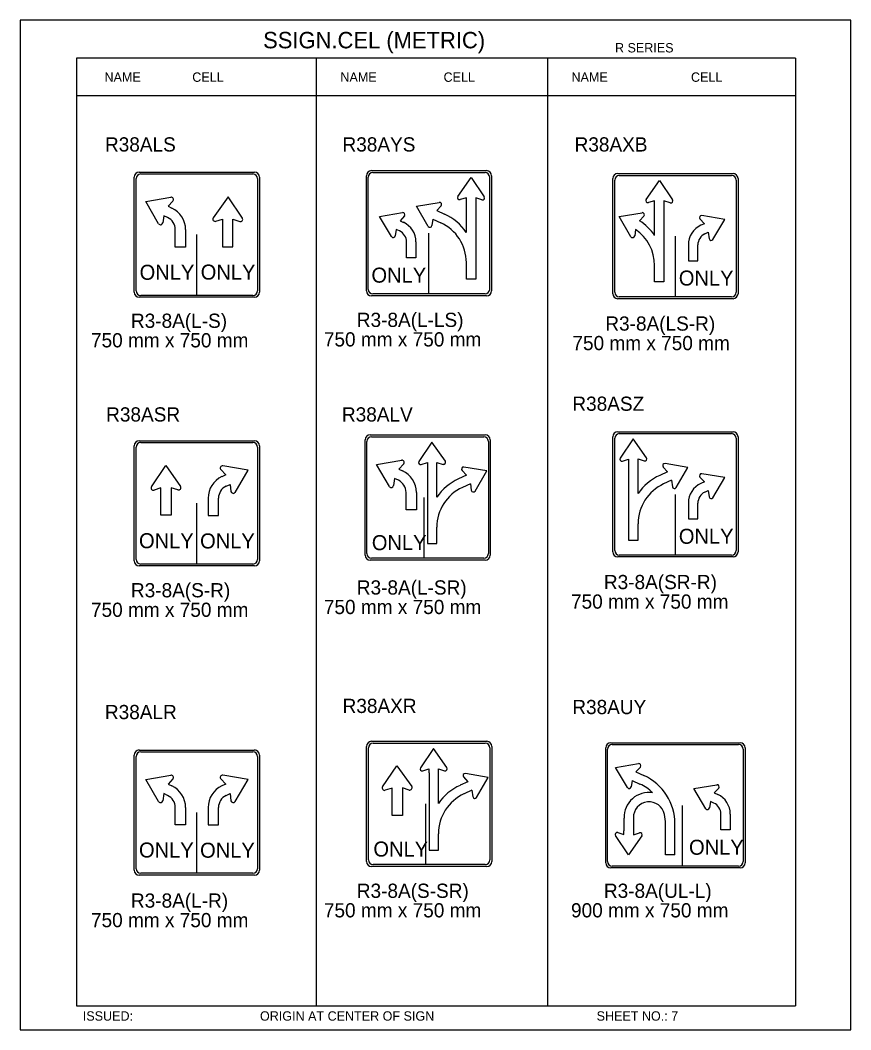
# Model space of a CAD drawing. Extents: x -12 to 6962, y -3756 to 679.
# Drawn here: x -11.9 to 163.4, y -5 to 208 of the extents above; entities that cross this region are included whole.
import ezdxf

# ---------------------------------------------------------------- set-up
doc = ezdxf.new("R2010")
doc.units = 0
for name, color, linetype in [('Level 1', 7, 'Continuous'), ('Level 2', 7, 'Continuous'), ('Level 3', 7, 'Continuous'), ('Level 63', 7, 'Continuous')]:
    doc.layers.add(name, color=color, linetype=linetype)

msp = doc.modelspace()

# ---------------------------------------------------------------- linework, layer by layer
at = {"layer": 'Level 1'}
for p, q in [((151.75, 200), (0, 200)), ((0, 200), (0, 0)), ((50.58, 200), (50.58, 0)), ((99.37, 200), (99.37, 0)), ((151.75, 200), (151.75, 0)), ((151.75, 192.08), (0, 192.08)), ((13.57, 175.59), (37.24, 175.59)), ((61.55, 151.24), (61.55, 174.92)), ((62.53, 175.9), (86.21, 175.9)), ((80.46, 170.82), (83.31, 174.84)), ((83.31, 174.84), (86.05, 170.76)), ((87.18, 174.92), (87.18, 151.24)), ((114.23, 175.68), (138.53, 175.68)), ((114.54, 175.28), (138.22, 175.28)), ((12.59, 150.94), (12.59, 174.61)), ((38.22, 174.61), (38.22, 150.94)), ((113.17, 150.32), (113.17, 174.62)), ((113.56, 150.63), (113.56, 174.31)), ((120.18, 170.21), (123.03, 174.22)), ((123.03, 174.22), (125.77, 170.15)), ((139.19, 174.31), (139.19, 150.63)), ((139.59, 174.62), (139.59, 150.32)), ((14.6, 169.76), (19.93, 170.67)), ((31.98, 170.74), (28.85, 166.32)), ((35, 166.26), (31.98, 170.74)), ((82.26, 170.56), (80.95, 170.17)), ((82.26, 169.74), (82.26, 170.56)), ((85.55, 170.12), (84.24, 170.54)), ((84.24, 170.54), (84.24, 169.75)), ((17.34, 165.09), (14.6, 169.76)), ((20.35, 169.87), (19.33, 168.76)), ((19.33, 168.76), (20.13, 168.4)), ((71.72, 168.76), (76.56, 169.59)), ((74.2, 164.52), (71.72, 168.76)), ((76.94, 168.86), (76.02, 167.85)), ((82.26, 163.24), (82.26, 169.74)), ((84.23, 169.75), (84.23, 153.42)), ((121.98, 169.95), (120.67, 169.55)), ((121.98, 169.13), (121.98, 169.95)), ((121.98, 162.63), (121.98, 169.13)), ((123.95, 169.14), (123.95, 152.81)), ((125.27, 169.5), (123.96, 169.93)), ((123.96, 169.93), (123.96, 169.14)), ((18.41, 166.78), (18.21, 165.29)), ((19.23, 166.4), (18.41, 166.78)), ((63.97, 166.62), (68.81, 167.44)), ((66.45, 162.37), (63.97, 166.62)), ((69.19, 166.72), (68.27, 165.7)), ((76.02, 167.85), (77.68, 167.09)), ((114.51, 166.59), (119.35, 167.42)), ((116.99, 162.35), (114.51, 166.59)), ((119.73, 166.69), (118.82, 165.69)), ((136.78, 166), (131.94, 166.83)), ((29.39, 165.6), (30.83, 166.04)), ((30.83, 166.04), (30.82, 165.13)), ((30.82, 165.13), (30.82, 160.24)), ((33, 160.24), (33, 165.14)), ((33.01, 165.14), (33.01, 166.02)), ((33.01, 166.02), (34.45, 165.55)), ((68.27, 165.7), (68.99, 165.37)), ((75.18, 166.05), (75, 164.69)), ((75.18, 166.05), (76.86, 165.28)), ((131.56, 166.1), (132.48, 165.09)), ((132.48, 165.09), (131.76, 164.76)), ((134.29, 161.76), (136.78, 166)), ((20.85, 160.17), (20.85, 163.86)), ((23.03, 163.85), (23.03, 160.17)), ((25.4, 162.78), (25.4, 162.78)), ((25.4, 162.78), (25.4, 162.78)), ((25.4, 149.96), (25.4, 162.78)), ((67.43, 163.9), (67.25, 162.55)), ((68.18, 163.56), (67.43, 163.9)), ((74.37, 163.08), (74.37, 163.08)), ((74.37, 150.27), (74.37, 163.08)), ((117.97, 163.88), (117.79, 162.52)), ((126.38, 162.47), (126.38, 162.47)), ((126.38, 162.47), (126.38, 162.47)), ((126.38, 149.65), (126.38, 162.47)), ((132.57, 162.95), (133.32, 163.29)), ((133.32, 163.29), (133.5, 161.93)), ((23.03, 160.17), (20.85, 160.17)), ((30.82, 160.24), (33, 160.24)), ((69.65, 157.89), (69.65, 161.25)), ((71.63, 161.24), (71.63, 157.89)), ((129.12, 160.63), (129.12, 157.28)), ((131.1, 157.28), (131.1, 160.64)), ((71.63, 157.89), (69.65, 157.89)), ((82.26, 153.42), (82.26, 156.88)), ((121.98, 152.81), (121.98, 156.26)), ((129.12, 157.28), (131.1, 157.28)), ((84.23, 153.42), (82.26, 153.42)), ((123.95, 152.81), (121.98, 152.81)), ((37.24, 149.96), (13.57, 149.96)), ((86.21, 150.27), (62.53, 150.27)), ((138.53, 149.26), (114.23, 149.26)), ((138.22, 149.65), (114.54, 149.65)), ((62.26, 120.12), (85.93, 120.12)), ((113.56, 96.12), (113.56, 119.8)), ((114.54, 120.78), (138.22, 120.78)), ((117.44, 119.72), (114.69, 115.64)), ((120.29, 115.7), (117.44, 119.72)), ((139.19, 119.8), (139.19, 96.12)), ((12.59, 94.24), (12.59, 117.91)), ((13.57, 118.89), (37.24, 118.89)), ((38.22, 117.91), (38.22, 94.24)), ((61.28, 95.46), (61.28, 119.14)), ((74.99, 118.97), (72.24, 114.9)), ((77.84, 114.96), (74.99, 118.97)), ((86.91, 119.14), (86.91, 95.46)), ((63.29, 114.29), (68.62, 115.2)), ((115.2, 115), (116.5, 115.42)), ((116.5, 115.42), (116.5, 114.63)), ((118.49, 114.62), (118.49, 115.44)), ((118.49, 115.44), (119.8, 115.05)), ((15.81, 109.56), (18.83, 114.04)), ((18.83, 114.04), (21.96, 109.62)), ((30.46, 113.18), (31.48, 112.06)), ((36.2, 113.06), (30.88, 113.97)), ((33.47, 108.39), (36.2, 113.06)), ((66.03, 109.62), (63.29, 114.29)), ((69.04, 114.4), (68.02, 113.29)), ((68.02, 113.29), (68.82, 112.92)), ((72.75, 114.25), (74.05, 114.68)), ((74.05, 114.68), (74.05, 113.88)), ((74.06, 113.88), (74.06, 97.56)), ((76.04, 113.88), (76.04, 114.7)), ((76.04, 114.7), (77.35, 114.3)), ((76.04, 107.38), (76.04, 113.88)), ((81.35, 113), (82.28, 111.99)), ((86.58, 112.9), (81.73, 113.72)), ((116.51, 114.63), (116.51, 98.3)), ((118.49, 108.12), (118.49, 114.62)), ((123.8, 113.74), (124.73, 112.73)), ((129.03, 113.64), (124.18, 114.47)), ((126.54, 109.39), (129.03, 113.64)), ((31.48, 112.06), (30.68, 111.7)), ((67.1, 111.31), (66.9, 109.81)), ((67.92, 110.93), (67.1, 111.31)), ((82.28, 111.99), (80.61, 111.22)), ((84.09, 108.65), (86.58, 112.9)), ((124.73, 112.73), (123.06, 111.97)), ((125.57, 110.93), (123.89, 110.16)), ((125.57, 110.93), (125.74, 109.57)), ((131.56, 111.6), (132.48, 110.58)), ((136.78, 111.5), (131.94, 112.32)), ((134.29, 107.25), (136.78, 111.5)), ((17.79, 109.32), (16.36, 108.85)), ((17.8, 108.44), (17.79, 109.32)), ((21.42, 108.9), (19.98, 109.34)), ((19.98, 109.34), (19.98, 108.43)), ((31.57, 109.7), (32.4, 110.08)), ((32.4, 110.08), (32.59, 108.59)), ((83.12, 110.18), (81.44, 109.42)), ((83.12, 110.18), (83.29, 108.83)), ((132.48, 110.58), (131.76, 110.25)), ((132.57, 108.44), (133.32, 108.78)), ((133.32, 108.78), (133.5, 107.43)), ((17.81, 103.54), (17.81, 108.44)), ((19.98, 108.43), (19.98, 103.54)), ((27.78, 107.15), (27.78, 103.47)), ((29.96, 103.47), (29.96, 107.16)), ((69.54, 104.69), (69.54, 108.39)), ((71.72, 108.38), (71.72, 104.69)), ((73.35, 94.49), (73.35, 107.3)), ((74.09, 107.3), (74.09, 107.3)), ((126.38, 107.96), (126.38, 107.96)), ((126.38, 107.96), (126.38, 107.96)), ((126.38, 95.15), (126.38, 107.96)), ((25.4, 106.08), (25.4, 106.08)), ((25.4, 93.26), (25.4, 106.08)), ((71.72, 104.69), (69.54, 104.69)), ((129.12, 106.12), (129.12, 102.77)), ((131.1, 102.77), (131.1, 106.13)), ((19.98, 103.54), (17.81, 103.54)), ((27.78, 103.47), (29.96, 103.47)), ((129.12, 102.77), (131.1, 102.77)), ((76.04, 97.56), (76.04, 101.01)), ((118.49, 98.3), (118.49, 101.76)), ((116.51, 98.3), (118.49, 98.3)), ((74.06, 97.56), (76.04, 97.56)), ((85.93, 94.49), (62.26, 94.49)), ((138.22, 95.15), (114.54, 95.15)), ((37.24, 93.26), (13.57, 93.26)), ((62.58, 55.45), (86.26, 55.45)), ((13.57, 53.61), (37.24, 53.61)), ((61.61, 30.8), (61.61, 54.47)), ((75.32, 54.3), (72.57, 50.23)), ((78.16, 50.29), (75.32, 54.3)), ((87.24, 54.47), (87.24, 30.8)), ((112.07, 30.49), (112.07, 54.17)), ((113.05, 55.14), (139.71, 55.14)), ((140.69, 54.17), (140.69, 30.49)), ((12.59, 28.96), (12.59, 52.63)), ((38.22, 52.63), (38.22, 28.96)), ((64.59, 46.22), (67.61, 50.7)), ((67.61, 50.7), (70.75, 46.28)), ((73.07, 49.58), (74.38, 50.01)), ((74.38, 50.01), (74.38, 49.22)), ((74.39, 49.22), (74.39, 32.89)), ((76.37, 49.21), (76.36, 50.03)), ((76.36, 50.03), (77.67, 49.63)), ((76.37, 42.71), (76.37, 49.21)), ((86.9, 48.23), (82.06, 49.05)), ((113.76, 50.31), (118.61, 51.14)), ((116.25, 46.06), (113.76, 50.31)), ((118.99, 50.41), (118.06, 49.4)), ((118.06, 49.4), (119.73, 48.64)), ((14.6, 47.78), (19.93, 48.69)), ((17.34, 43.11), (14.6, 47.78)), ((20.35, 47.89), (19.33, 46.78)), ((30.46, 47.89), (31.48, 46.78)), ((36.2, 47.78), (30.88, 48.69)), ((33.47, 43.11), (36.2, 47.78)), ((82.61, 47.32), (80.94, 46.56)), ((81.68, 48.33), (82.61, 47.32)), ((84.42, 43.98), (86.9, 48.23)), ((117.22, 47.6), (117.05, 46.24)), ((117.22, 47.6), (118.9, 46.83)), ((18.41, 44.8), (18.21, 43.31)), ((19.23, 44.42), (18.41, 44.8)), ((19.33, 46.78), (20.13, 46.42)), ((31.48, 46.78), (30.68, 46.42)), ((31.57, 44.42), (32.4, 44.8)), ((32.4, 44.8), (32.59, 43.31)), ((66.58, 45.98), (65.15, 45.51)), ((66.59, 45.1), (66.58, 45.98)), ((66.59, 40.2), (66.59, 45.1)), ((70.21, 45.56), (68.77, 46)), ((68.77, 46), (68.77, 45.09)), ((68.77, 45.09), (68.77, 40.2)), ((83.44, 45.52), (81.77, 44.75)), ((83.44, 45.52), (83.62, 44.16)), ((130.28, 45.86), (135.13, 46.69)), ((132.77, 41.61), (130.28, 45.86)), ((135.51, 45.96), (134.58, 44.95)), ((134.58, 44.95), (135.31, 44.62)), ((73.68, 29.82), (73.68, 42.63)), ((74.42, 42.63), (74.42, 42.63)), ((133.75, 43.15), (133.57, 41.79)), ((134.49, 42.81), (133.75, 43.15)), ((20.85, 38.19), (20.85, 41.88)), ((23.03, 41.87), (23.03, 38.19)), ((25.4, 40.8), (25.4, 40.8)), ((25.4, 27.98), (25.4, 40.8)), ((27.78, 41.87), (27.78, 38.19)), ((29.96, 38.19), (29.96, 41.88)), ((126.38, 42.33), (126.38, 42.33)), ((127.87, 29.51), (127.87, 42.33)), ((135.96, 37.14), (135.96, 40.5)), ((68.77, 40.2), (66.59, 40.2)), ((115.53, 36.94), (115.53, 39.65)), ((117.51, 39.7), (117.51, 36.95)), ((124.3, 31.85), (124.3, 38.43)), ((126.28, 31.85), (126.28, 38.43)), ((137.94, 40.49), (137.94, 37.14)), ((23.03, 38.19), (20.85, 38.19)), ((27.78, 38.19), (29.96, 38.19)), ((76.37, 32.89), (76.37, 36.34)), ((114.22, 36.57), (115.52, 36.15)), ((115.52, 36.15), (115.52, 36.94)), ((117.51, 36.95), (117.51, 36.12)), ((117.51, 36.12), (118.82, 36.52)), ((137.94, 37.14), (135.96, 37.14)), ((116.46, 31.85), (113.71, 35.93)), ((119.31, 35.87), (116.46, 31.85)), ((74.39, 32.89), (76.37, 32.89)), ((126.28, 31.85), (124.3, 31.85)), ((37.24, 27.98), (13.57, 27.98)), ((86.26, 29.82), (62.58, 29.82)), ((139.71, 29.51), (113.05, 29.51)), ((0, 0), (151.75, 0))]:
    msp.add_line(p, q, dxfattribs=at)
for centre, radius, start, end in [((13.57, 174.61), 0.977, 90, 180), ((37.24, 174.61), 0.977, 0, 90), ((62.53, 174.92), 0.977, 90, 180), ((86.21, 174.92), 0.977, 0, 90), ((114.23, 174.62), 1.06, 90, 180), ((114.54, 174.31), 0.977, 90, 180), ((138.22, 174.31), 0.977, 0, 90), ((138.53, 174.62), 1.06, 0, 90), ((19.98, 170.2), 0.482, 318.677, 97.1175), ((80.83, 170.59), 0.439, 147.4967, 286.0699), ((85.68, 170.54), 0.438, 252.9852, 31.4257), ((18.03, 163.86), 5, 359.9807, 65.3304), ((76.61, 169.16), 0.438, 318.677, 97.1175), ((120.55, 169.98), 0.439, 147.4967, 286.0699), ((125.4, 169.93), 0.438, 252.9852, 31.4257), ((18.02, 163.85), 2.82, 0.0924, 64.7362), ((29.26, 166.07), 0.483, 147.4967, 286.0699), ((34.59, 166.01), 0.482, 252.9852, 31.4257), ((68.86, 167.01), 0.438, 318.677, 97.1175), ((73.01, 156.88), 11.23, 34.5604, 65.4104), ((119.4, 166.99), 0.438, 318.677, 97.1175), ((131.89, 166.4), 0.438, 82.8825, 221.323), ((17.74, 165.36), 0.483, 213.1885, 351.7617), ((67.08, 161.25), 4.55, 359.9807, 65.3304), ((74.57, 164.76), 0.439, 213.1885, 351.7617), ((73.01, 156.88), 9.25, 0, 65.4104), ((112.73, 156.26), 11.23, 34.5604, 57.1536), ((133.66, 160.63), 4.55, 114.6696, 180.0193), ((66.82, 162.61), 0.439, 213.1885, 351.7617), ((67.08, 161.24), 2.56, 0.0924, 64.7362), ((117.36, 162.59), 0.439, 213.1885, 351.7617), ((112.73, 156.26), 9.25, 0, 55.4773), ((133.67, 160.63), 2.56, 115.2638, 179.9076), ((133.93, 162), 0.439, 188.2383, 326.8115), ((13.57, 150.94), 0.977, 180, 270), ((37.24, 150.94), 0.977, 270, 0), ((62.53, 151.24), 0.977, 180, 270), ((86.21, 151.24), 0.977, 270, 0), ((114.23, 150.32), 1.06, 180, 270), ((114.54, 150.63), 0.977, 180, 270), ((138.22, 150.63), 0.977, 270, 0), ((138.53, 150.32), 1.06, 270, 0), ((62.26, 119.14), 0.977, 90, 180), ((85.93, 119.14), 0.977, 0, 90), ((114.54, 119.8), 0.977, 90, 180), ((138.22, 119.8), 0.977, 0, 90), ((13.57, 117.91), 0.977, 90, 180), ((37.24, 117.91), 0.977, 0, 90), ((68.67, 114.72), 0.482, 318.677, 97.1175), ((115.07, 115.42), 0.438, 148.5743, 287.0148), ((119.91, 115.47), 0.439, 253.9301, 32.5033), ((30.82, 113.5), 0.482, 82.8825, 221.323), ((72.62, 114.67), 0.438, 148.5743, 287.0148), ((77.46, 114.73), 0.439, 253.9301, 32.5033), ((81.68, 113.29), 0.438, 82.8825, 221.323), ((124.14, 114.04), 0.438, 82.8825, 221.323), ((32.77, 107.16), 5, 114.6696, 180.0193), ((66.72, 108.38), 2.82, 0.0924, 64.7362), ((66.72, 108.38), 5, 359.9807, 65.3304), ((85.29, 101.01), 11.23, 114.5896, 145.4396), ((127.74, 101.76), 11.23, 114.5896, 145.4396), ((131.89, 111.89), 0.438, 82.8825, 221.323), ((16.22, 109.31), 0.482, 148.5743, 287.0148), ((21.55, 109.37), 0.483, 253.9301, 32.5033), ((32.78, 107.15), 2.82, 115.2638, 179.9076), ((66.43, 109.89), 0.483, 213.1885, 351.7617), ((85.29, 101.01), 9.25, 114.5896, 180), ((83.73, 108.9), 0.439, 188.2383, 326.8115), ((127.74, 101.76), 9.25, 114.5896, 180), ((126.18, 109.64), 0.439, 188.2383, 326.8115), ((133.66, 106.13), 4.55, 114.6696, 180.0193), ((33.07, 108.66), 0.483, 188.2383, 326.8115), ((133.67, 106.12), 2.56, 115.2638, 179.9076), ((133.93, 107.49), 0.439, 188.2383, 326.8115), ((114.54, 96.12), 0.977, 180, 270), ((138.22, 96.12), 0.977, 270, 0), ((13.57, 94.24), 0.977, 180, 270), ((37.24, 94.24), 0.977, 270, 0), ((62.26, 95.46), 0.977, 180, 270), ((85.93, 95.46), 0.977, 270, 0), ((62.58, 54.47), 0.977, 90, 180), ((86.26, 54.47), 0.977, 0, 90), ((13.57, 52.63), 0.977, 90, 180), ((37.24, 52.63), 0.977, 0, 90), ((113.05, 54.17), 0.977, 90, 180), ((139.71, 54.17), 0.977, 0, 90), ((118.65, 50.71), 0.438, 318.677, 97.1175), ((72.94, 50.01), 0.438, 148.5743, 287.0148), ((77.79, 50.06), 0.439, 253.9301, 32.5033), ((82.01, 48.62), 0.438, 82.8825, 221.323), ((19.98, 48.22), 0.482, 318.677, 97.1175), ((30.82, 48.22), 0.482, 82.8825, 221.323), ((115.05, 38.42), 11.23, 0.0008, 65.4104), ((18.03, 41.88), 5, 359.9807, 65.3304), ((32.77, 41.88), 5, 114.6696, 180.0193), ((65, 45.97), 0.482, 148.5743, 287.0148), ((70.33, 46.03), 0.483, 253.9301, 32.5033), ((85.61, 36.34), 11.23, 114.5896, 145.4396), ((120.82, 39.77), 5.29, 81.8031, 181.26), ((116.61, 46.31), 0.439, 213.1885, 351.7617), ((115.05, 38.42), 9.25, 45.1774, 65.4104), ((135.18, 46.25), 0.438, 318.677, 97.1175), ((17.74, 43.38), 0.483, 213.1885, 351.7617), ((18.02, 41.87), 2.82, 0.0924, 64.7362), ((32.78, 41.87), 2.82, 115.2638, 179.9076), ((33.07, 43.38), 0.483, 188.2383, 326.8115), ((85.61, 36.34), 9.25, 114.5896, 180), ((84.06, 44.23), 0.439, 188.2383, 326.8115), ((120.82, 39.77), 3.31, 11.1431, 181.26), ((133.4, 40.49), 2.56, 0.0924, 64.7362), ((133.4, 40.49), 4.55, 359.9807, 65.3304), ((133.13, 41.86), 0.439, 213.1885, 351.7617), ((115.05, 38.42), 9.25, 0, 12.404), ((114.09, 36.15), 0.438, 72.9852, 211.4257), ((118.93, 36.1), 0.439, 327.4967, 106.0699), ((62.58, 30.8), 0.977, 180, 270), ((86.26, 30.8), 0.977, 270, 0), ((113.05, 30.49), 0.977, 180, 270), ((139.71, 30.49), 0.977, 270, 0), ((13.57, 28.96), 0.977, 180, 270), ((37.24, 28.96), 0.977, 270, 0)]:
    msp.add_arc(centre, radius, start, end, dxfattribs=at)
at = {"layer": 'Level 3'}
for p, q in [((12.2, 150.62), (12.2, 174.93)), ((13.25, 175.98), (37.55, 175.98)), ((38.61, 174.93), (38.61, 150.62)), ((61.16, 150.93), (61.16, 175.23)), ((62.22, 176.29), (86.52, 176.29)), ((87.58, 175.23), (87.58, 150.93)), ((114.23, 175.68), (138.53, 175.68)), ((113.17, 150.32), (113.17, 174.62)), ((139.59, 174.62), (139.59, 150.32)), ((37.55, 149.57), (13.25, 149.57)), ((86.52, 149.87), (62.22, 149.87)), ((138.53, 149.26), (114.23, 149.26)), ((60.89, 95.15), (60.89, 119.45)), ((61.94, 120.51), (86.24, 120.51)), ((87.3, 119.45), (87.3, 95.15)), ((113.17, 95.81), (113.17, 120.11)), ((114.23, 121.17), (138.53, 121.17)), ((139.59, 120.11), (139.59, 95.81)), ((12.2, 93.93), (12.2, 118.23)), ((13.25, 119.28), (37.55, 119.28)), ((38.61, 118.23), (38.61, 93.93)), ((86.24, 94.09), (61.94, 94.09)), ((138.53, 94.75), (114.23, 94.75)), ((37.55, 92.87), (13.25, 92.87)), ((62.27, 55.84), (86.57, 55.84)), ((112.74, 55.53), (140.02, 55.53)), ((13.25, 54), (37.55, 54)), ((61.21, 30.48), (61.21, 54.78)), ((87.63, 54.78), (87.63, 30.48)), ((111.68, 30.18), (111.68, 54.48)), ((141.08, 54.48), (141.08, 30.18)), ((12.2, 28.64), (12.2, 52.95)), ((38.61, 52.95), (38.61, 28.64)), ((86.57, 29.43), (62.27, 29.43)), ((140.02, 29.12), (112.74, 29.12)), ((37.55, 27.59), (13.25, 27.59))]:
    msp.add_line(p, q, dxfattribs=at)
for centre, start, end in [((13.25, 174.93), 90, 180), ((37.55, 174.93), 0, 90), ((62.22, 175.23), 90, 180), ((86.52, 175.23), 0, 90), ((114.23, 174.62), 90, 180), ((138.53, 174.62), 0, 90), ((13.25, 150.62), 180, 270), ((37.55, 150.62), 270, 0), ((62.22, 150.93), 180, 270), ((86.52, 150.93), 270, 0), ((114.23, 150.32), 180, 270), ((138.53, 150.32), 270, 0), ((61.94, 119.45), 90, 180), ((86.24, 119.45), 0, 90), ((114.23, 120.11), 90, 180), ((138.53, 120.11), 0, 90), ((13.25, 118.23), 90, 180), ((37.55, 118.23), 0, 90), ((13.25, 93.93), 180, 270), ((37.55, 93.93), 270, 0), ((61.94, 95.15), 180, 270), ((86.24, 95.15), 270, 0), ((114.23, 95.81), 180, 270), ((138.53, 95.81), 270, 0), ((62.27, 54.78), 90, 180), ((86.57, 54.78), 0, 90), ((112.74, 54.48), 90, 180), ((140.02, 54.48), 0, 90), ((13.25, 52.95), 90, 180), ((37.55, 52.95), 0, 90), ((62.27, 30.48), 180, 270), ((86.57, 30.48), 270, 0), ((112.74, 30.18), 180, 270), ((140.02, 30.18), 270, 0), ((13.25, 28.64), 180, 270), ((37.55, 28.64), 270, 0)]:
    msp.add_arc(centre, 1.06, start, end, dxfattribs=at)
at = {"layer": 'Level 63'}
msp.add_lwpolyline([(-11.88, -5.05), (163.38, -5.05), (163.38, 208.05), (-11.88, 208.05)], close=True, dxfattribs=at)

# ---------------------------------------------------------------- texts
at = {"layer": 'Level 1'}
for p in [(13.32, 153.25), (26.21, 153.3), (62.24, 152.65), (127.1, 152.04), (127.1, 97.53), (13.19, 96.6), (26.08, 96.55), (62.32, 96.19), (13.19, 31.32), (26.08, 31.27), (62.65, 31.52), (129.25, 31.9)]:
    msp.add_text('ONLY', height=3.17, dxfattribs=at).set_placement(p)
at = {"layer": 'Level 2'}
for s, p in [('R38ALS', (6.01, 180.33)), ('R38AYS', (56.13, 180.33)), ('R38AXB', (105.1, 180.33)), ('R38ASZ', (104.63, 125.6)), ('R38ASR', (6.26, 123.34)), ('R38ALV', (56.01, 123.34)), ('R38AXR', (56.15, 61.82)), ('R38AUY', (104.62, 61.58)), ('R38ALR', (6, 60.52))]:
    msp.add_text(s, height=3, dxfattribs=at).set_placement(p)
at = {"layer": 'Level 3'}
for s, height, p in [('SSIGN.CEL (METRIC)', 3.4642, (39.38, 202.11)), ('R SERIES', 1.979, (113.63, 201.24)), ('NAME', 1.98, (5.91, 195.04)), ('CELL', 1.98, (24.43, 195.04)), ('NAME', 1.98, (55.69, 195.04)), ('CELL', 1.98, (77.45, 195.04)), ('NAME', 1.98, (104.45, 195.04)), ('CELL', 1.98, (129.66, 195.04)), ('R3-8A(L-S)', 3, (11.49, 143.11)), ('R3-8A(L-LS)', 3, (59.15, 143.3)), ('R3-8A(LS-R)', 3, (111.59, 142.52)), ('750 mm x 750 mm', 3, (3.06, 138.99)), ('750 mm x 750 mm', 3, (52.2, 139.18)), ('750 mm x 750 mm', 3, (104.64, 138.4)), ('R3-8A(L-SR)', 3, (59.15, 86.82)), ('R3-8A(SR-R)', 3, (111.29, 87.96)), ('R3-8A(S-R)', 3, (11.49, 86.23)), ('750 mm x 750 mm', 3, (52.2, 82.7)), ('750 mm x 750 mm', 3, (104.35, 83.84)), ('750 mm x 750 mm', 3, (3.06, 82.11)), ('R3-8A(S-SR)', 3, (59.15, 22.8)), ('R3-8A(UL-L)', 3, (111.29, 22.8)), ('R3-8A(L-R)', 3, (11.49, 20.73)), ('750 mm x 750 mm', 3, (52.2, 18.68)), ('900 mm x 750 mm', 3, (104.35, 18.68)), ('750 mm x 750 mm', 3, (3.06, 16.61)), ('ISSUED:', 1.98, (1.34, -3.12)), ('ORIGIN AT CENTER OF SIGN', 1.9795, (38.72, -3.12)), ('SHEET NO.: 7', 1.9795, (109.75, -3.12))]:
    msp.add_text(s, height=height, dxfattribs=at).set_placement(p)

doc.saveas('drawing.dxf')
